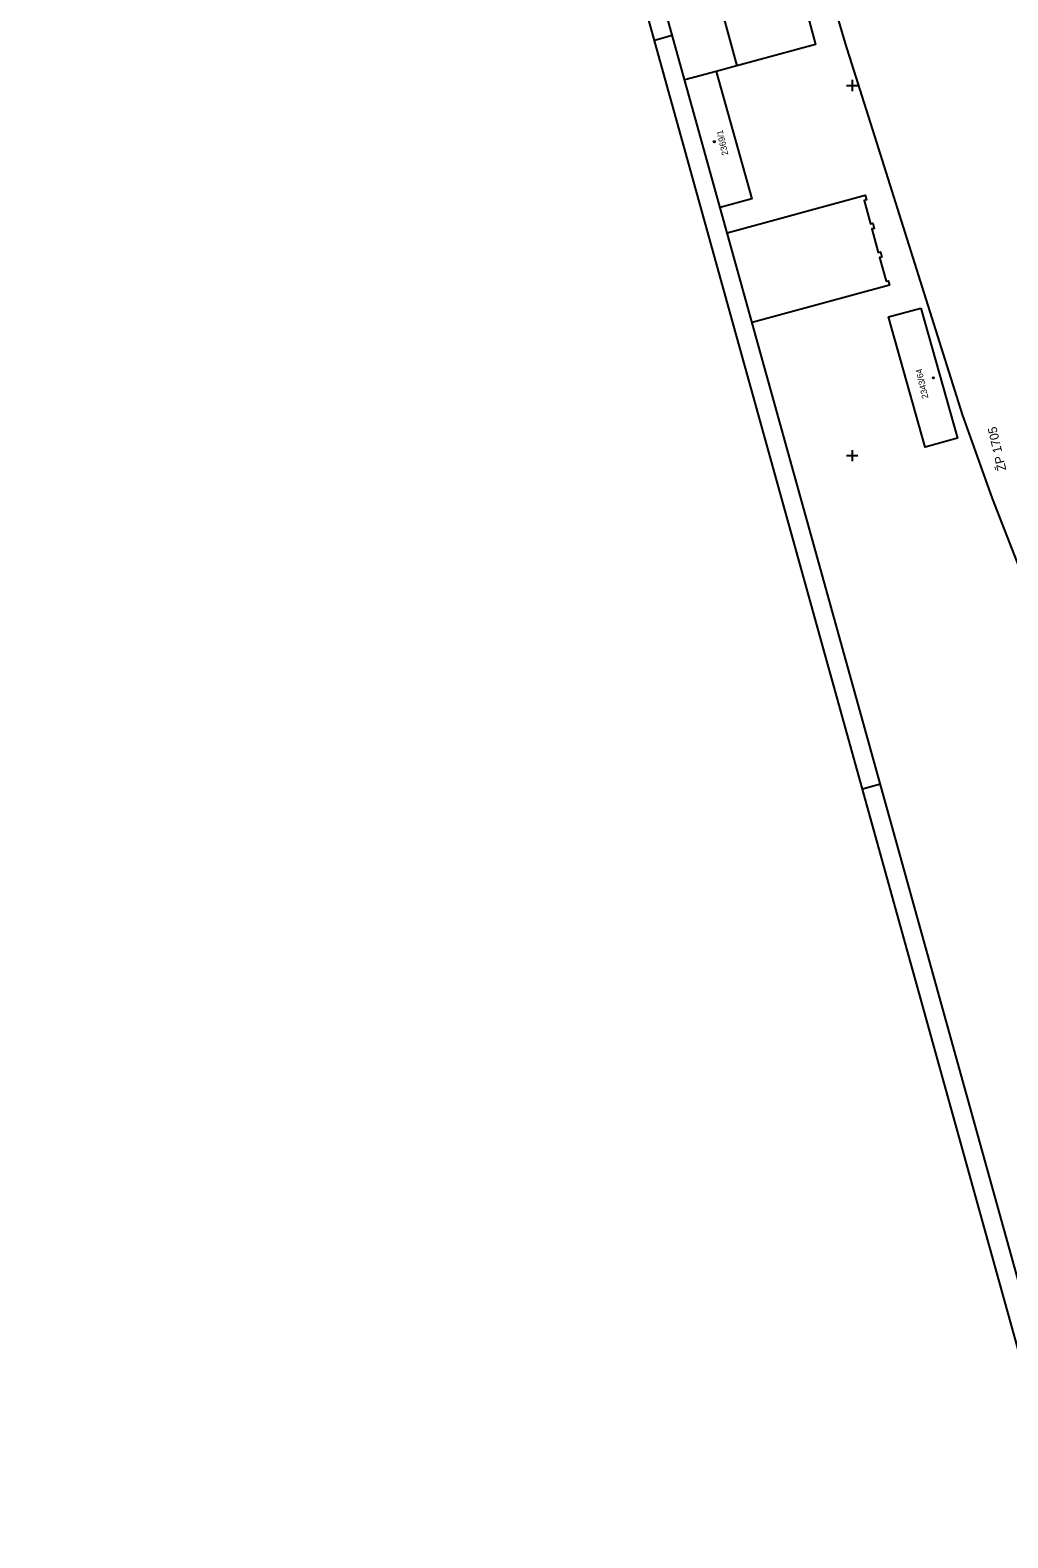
# Model space of a CAD drawing. Extents: x -821122 to -820555, y -1070892 to -1069801.
# Drawn here: x -821122.1 to -820857.9, y -1070892.4 to -1070485 of the extents above; entities that cross this region are included whole.
import ezdxf

# ---------------------------------------------------------------- set-up
doc = ezdxf.new("R2010")
doc.units = 0
for name, color, linetype in [('Hranice drážního pozemku', 7, 'Continuous'), ('Hranice parcel', 7, 'Continuous'), ('Parcelní čísla', 7, 'Continuous'), ('Ram', 7, 'Continuous'), ('Vrstva 61', 7, 'Continuous'), ('ZBP', 7, 'Continuous'), ('Značky budov', 7, 'Continuous')]:
    doc.layers.add(name, color=color, linetype=linetype)

msp = doc.modelspace()

# ---------------------------------------------------------------- linework, layer by layer
at = {"layer": 'Hranice drážního pozemku'}
msp.add_lwpolyline([(-820768.36, -1070867.01), (-820772.76, -1070853.45), (-820780.56, -1070834.55), (-820786.59, -1070821.38), (-820797.89, -1070798.01), (-820802.49, -1070786.9), (-820807.86, -1070771.6), (-820839.34, -1070671.73), (-820847.49, -1070649.05), (-820862.12, -1070611.55), (-820870.18, -1070588.9), (-820893.88, -1070513.71), (-820901.78, -1070488.65), (-820908.48, -1070465.88), (-820912.77, -1070441.75), (-820907.91, -1070440.8), (-820914.43, -1070404.83), (-820920.34, -1070372.85), (-820926.76, -1070341.17), (-820933.59, -1070313.73), (-820939.94, -1070294.5), (-820946.33, -1070279.59), (-820953.63, -1070265.09), (-820959.73, -1070254.91)], dxfattribs=at)
at = {"layer": 'Hranice parcel'}
for p, q in [((-820955.07, -1070406.16), (-820931.21, -1070494.68)), ((-820931.21, -1070494.68), (-820936.77, -1070496.18)), ((-820936.77, -1070496.18), (-820945.25, -1070498.47))]:
    msp.add_line(p, q, dxfattribs=at)
for points in [[(-820768.36, -1070867.01), (-820772.76, -1070853.45), (-820780.56, -1070834.55), (-820786.59, -1070821.38), (-820797.89, -1070798.01), (-820802.49, -1070786.9), (-820807.86, -1070771.6), (-820839.34, -1070671.73), (-820847.49, -1070649.05), (-820862.12, -1070611.55), (-820870.18, -1070588.9), (-820893.88, -1070513.71), (-820901.78, -1070488.65), (-820908.48, -1070465.88), (-820912.77, -1070441.75), (-820907.91, -1070440.8), (-820914.43, -1070404.83), (-820920.34, -1070372.85), (-820926.76, -1070341.17), (-820933.59, -1070313.73), (-820939.94, -1070294.5), (-820946.33, -1070279.59), (-820953.63, -1070265.09), (-820959.73, -1070254.91)], [(-820933.62, -1070400.37), (-820926.16, -1070398.36), (-820918.36, -1070427.34), (-820925.8, -1070429.59), (-820909.9, -1070488.92), (-820931.21, -1070494.68)], [(-820936.77, -1070496.18), (-820927.12, -1070530.65), (-820935.67, -1070532.95)], [(-820933.76, -1070539.85), (-820896.5, -1070529.65), (-820896.17, -1070530.88), (-820896.75, -1070531.03), (-820895.04, -1070537.38), (-820894.46, -1070537.22), (-820894.09, -1070538.61), (-820894.67, -1070538.77), (-820892.95, -1070545.12), (-820892.38, -1070544.96), (-820892, -1070546.35), (-820892.58, -1070546.51), (-820890.86, -1070552.89), (-820890.28, -1070552.73), (-820889.96, -1070553.93), (-820927.03, -1070564.07)], [(-820881.48, -1070560.15), (-820871.53, -1070595.32), (-820880.27, -1070597.68), (-820890.22, -1070562.51), (-820881.48, -1070560.15)]]:
    msp.add_lwpolyline(points, dxfattribs=at)
at = {"layer": 'Ram'}
for p, q in [((-820953.43, -1070487.71), (-820948.62, -1070486.37)), ((-820897.21, -1070690.04), (-820892.39, -1070688.71))]:
    msp.add_line(p, q, dxfattribs=at)
for points in [[(-820837.51, -1070886.22), (-821115.94, -1069884.19), (-820839.42, -1069807.35)], [(-820840.99, -1070892.38), (-821122.1, -1069880.71)]]:
    msp.add_lwpolyline(points, dxfattribs=at)
at = {"layer": 'Vrstva 61'}
for p, q in [((-820900, -1070498.5), (-820900, -1070501.5)), ((-820901.5, -1070500), (-820898.5, -1070500)), ((-820901.5, -1070600), (-820898.5, -1070600)), ((-820900, -1070598.5), (-820900, -1070601.5))]:
    msp.add_line(p, q, dxfattribs=at)
at = {"layer": 'Značky budov'}
for centre in [(-820937.26, -1070515.2), (-820878.09, -1070578.99)]:
    msp.add_circle(centre, 0.175, dxfattribs=at)

# ---------------------------------------------------------------- texts
at = {"layer": 'Parcelní čísla'}
for s, p in [('2369/1', (-820933.46, -1070518.66)), ('2343/64', (-820879.39, -1070584.4))]:
    msp.add_text(s, height=1.7, rotation=103, dxfattribs=at).set_placement(p)
at = {"layer": 'ZBP'}
msp.add_text('ŽP 1705', height=2.4, rotation=103, dxfattribs=at).set_placement((-820858.35, -1070603.82))

doc.saveas('drawing.dxf')
